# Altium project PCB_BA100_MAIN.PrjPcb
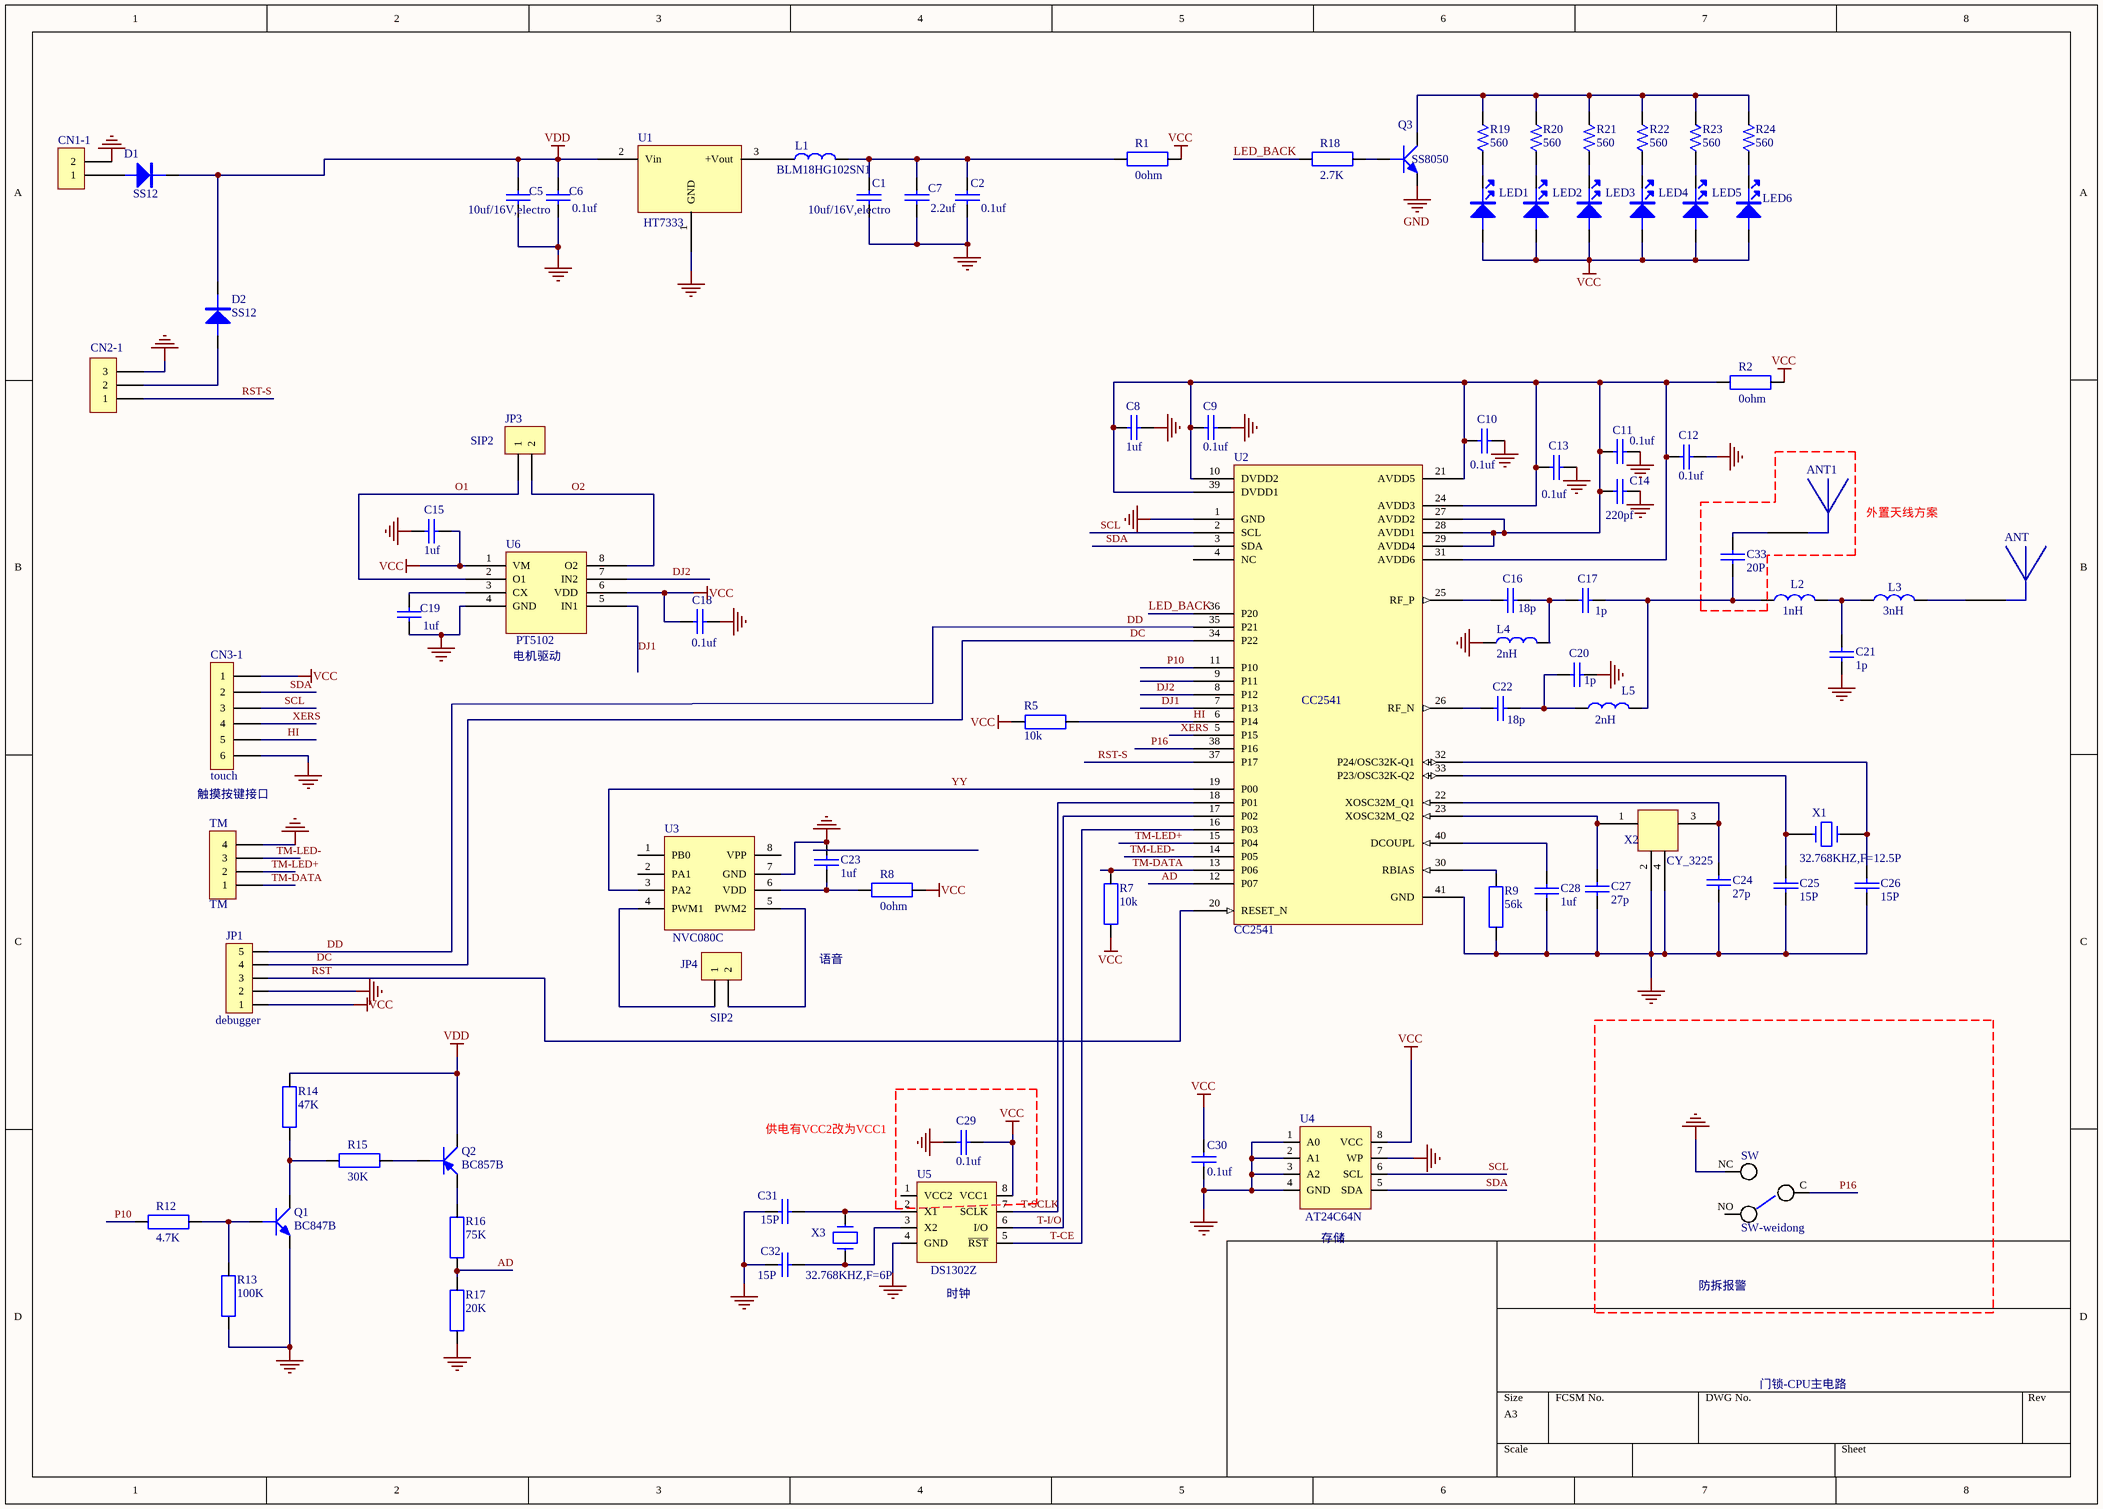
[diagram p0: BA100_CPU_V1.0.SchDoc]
1 sheet, 85 parts. Net scope: global (net labels, ports and power ports of the same name join across sheets).
Board file: BA100_CPU_V1.0.PcbDoc

## Sheet BA100_CPU_V1.0.SchDoc
size A3

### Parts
ANT  ANT  [ANT]  (value not drawn)
ANT1  ANT  [IPEX]  (value not drawn)
C1  10uf/16V,electro  [ECAP_10U_4.3*4.3]
C2  0.1uf  [PC7-*****-KO-0A_0603_TDK]
C5  10uf/16V,electro  [ECAP_10U_4.3*4.3]
C6  0.1uf  [PC5-*****-**-0A_0603_TDK]
C7  2.2uf  [PC5-*****-**-0A_0603_TDK]
C8  1uf  [PC5-*****-**-0A_0603_TDK]
C9  0.1uf  [PC7-*****-KO-0A_0603_TDK]
C10  0.1uf  [PC5-*****-**-0A_0603_TDK]
C11  0.1uf  [PC7-*****-KQA0A_0402_YAGEO]
C12  0.1uf  [PC7-*****-KQA0A_0402_YAGEO]
C13  0.1uf  [PC7-*****-KQA0A_0402_YAGEO]
C14  220pf  [PC7-*****-KQA0A_0402_YAGEO]
C15  1uf  [PC5-*****-**-0A_0603_TDK]
C16  18p  [PC7-*****-KQA0A_0402_YAGEO]
C17  1p  [PC7-*****-KQA0A_0402_YAGEO]
C18  0.1uf  [PC5-*****-**-0A_0603_TDK]
C19  1uf  [PC5-*****-**-0A_0603_TDK]
C20  1p  [PC7-*****-KQA0A_0402_YAGEO]
C21  1p  [PC7-*****-KQA0A_0402_YAGEO]
C22  18p  [PC7-*****-KQA0A_0402_YAGEO]
C23  1uf  [PC5-*****-**-0A_0603_TDK]
C24  27p  [PC7-*****-KO-0A_0603_TDK]
C25  15P  [PC5-*****-**-0A_0603_TDK]
C26  15P  [PC7-*****-KO-0A_0603_TDK]
C27  27p  [PC7-*****-KO-0A_0603_TDK]
C28  1uf  [PC5-*****-**-0A_0603_TDK]
C29  0.1uf  [PC7-*****-KO-0A_0603_TDK]
C30  0.1uf  [PC5-*****-**-0A_0603_TDK]
C31  15P  [PC7-*****-KO-0A_0603_TDK]
C32  15P  [PC7-*****-KO-0A_0603_TDK]
C33  20P  [PC7-*****-KQA0A_0402_YAGEO]
CN1-1  CN1  [PH2.0-2PIN-SMT]  (value not drawn)
CN2-1  CN2  [PH2.0-3PIN-SMT]  (value not drawn)
CN3-1  touch  [PH1.25-6PIN-SMT]
D1  SS12  [SS12-DIDEO]
D2  SS12  [SS12-DIDEO]
JP1  debugger  [ISCP-5PIN]
JP3  SIP2  [PH2.0-2PIN-LSMT1]
JP4  SIP2  [PH2.0-2PIN-LSMT1]
L1  BLM18HG102SN1  [PC7-*****-KO-0A_0603_TDK]
L2  1nH  [PC5-*****-**-0A_0402_TDK]
L3  3nH  [PC5-*****-**-0A_0402_TDK]
L4  2nH  [PC5-*****-**-0A_0402_TDK]
L5  2nH  [PC5-*****-**-0A_0402_TDK]
LED1  MA2X335  [LED-0805]  (value not drawn)
LED2  MA2X335  [LED-0805]  (value not drawn)
LED3  MA2X335  [LED-0805]  (value not drawn)
LED4  MA2X335  [LED-0805]  (value not drawn)
LED5  MA2X335  [LED-0805]  (value not drawn)
LED6  MA2X335  [LED-0805]  (value not drawn)
Q1  BC847B  [PTR-C0025-00-2A_2SC1623]
Q2  BC857B  [PTR-C0025-00-2A_2SC1623]
Q3  SS8050  [PTR-C0025-00-2A_2SC1623]
R1  0ohm  [PRC-*****-AM-0A_0603]
R2  0ohm  [PRC-*****-AM-0A_0603]
R5  10k  [PRC-*****-AM-0A_0603]
R7  10k  [PRC-*****-AM-0A_0603]
R8  0ohm  [PRC-*****-AM-0A_0603]
R9  56k  [PRC-*****-BM-0A_0402]
R12  4.7K  [PRC-*****-AM-0A_0603]
R13  100K  [PRC-*****-AM-0A_0603]
R14  47K  [PRC-*****-AM-0A_0603]
R15  30K  [PRC-*****-AM-0A_0603]
R16  75K  [PRC-*****-AM-0A_0603]
R17  20K  [PRC-*****-AM-0A_0603]
R18  2.7K  [PRC-*****-AM-0A_0603]
R19  560  [PRC-*****-AM-0A_0603]
R20  560  [PRC-*****-AM-0A_0603]
R21  560  [PRC-*****-AM-0A_0603]
R22  560  [PRC-*****-AM-0A_0603]
R23  560  [PRC-*****-AM-0A_0603]
R24  560  [PRC-*****-AM-0A_0603]
SW  SW-weidong  [SW-weidong]
TM  TM  [PH2.0-4PIN-SMT]
U1  HT7333  [SOT89]
U2  CC2541  [CC2530_QFN40]
U3  NVC080C  [SOP-8]
U4  AT24C64N  [PIC-00570-40-2A_93LC46B]
U5  DS1302Z  [PIC-00570-40-2A_93LC46B]
U6  PT5102  [PT5102]
X1  32.768KHZ,F=12.5P  [FC-135]
X2  CY_3225  [CY_3225]
X3  32.768KHZ,F=6P  [FC-135]

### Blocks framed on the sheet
防拆报警: SW

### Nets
GND: C1.1 C2.1 C5.1 C6.1 C7.2 C8.2 C9.2 C10.2 C11.2 C12.2 C13.2 C14.1 C15.1 C18.1 C19.1 C20.2 C21.1 C23.2 C24.1 C25.1 C26.1 C27.1 C28.1 C29.2 C30.1 C31.2 C32.2 CN1-1.2 CN2-1.3 CN3-1.6 JP1.2 L4.1 Q1.E Q3.E R9.2 R13.1 R17.1 SW.NC TM.4 U1.1(GND) U2.1(GND) U2.41(GND) U3.7(GND) U4.1(A0) U4.2(A1) U4.3(A2) U4.4(GND) U4.7(WP) U5.4(GND) U6.4(GND) X2.2 X2.4
VCC: C15.2 C18.2 C29.1 C30.2 CN3-1.1 JP1.1 LED1.A LED2.A LED3.A LED4.A LED5.A LED6.A R1.2 R2.2 R5.1 R7.1 R8.2 U4.8(VCC) U5.8(VCC1) U6.1(VM) U6.6(VDD)
VDD: C5.2 C6.2 D1.1 D2.1 Q2.C R14.2 U1.2(Vin)
AD: R16.1 R17.2 U2.12(P07)
DC: JP1.4 U2.34(P22)
DD: JP1.5 U2.35(P21)
DJ1: U2.7(P13) U6.5(IN1)
DJ2: U2.8(P12) U6.7(IN2)
HI: CN3-1.5 R5.2 U2.6(P14)
LED_BACK: R18.1 U2.36(P20)
O1: JP3.1 U6.2(O1)
O2: JP3.2 U6.8(O2)
P10: R12.1 U2.11(P10)
P16: SW.C U2.38(P16)
RST: JP1.3 U2.20(RESET_N)
RST-S: CN2-1.1 U2.37(P17)
SCL: CN3-1.3 U2.2(SCL) U4.6(SCL)
SDA: CN3-1.2 U2.3(SDA) U4.5(SDA)
T-CE: U2.16(P03) U5.5(~{RST})
T-I/O: U2.17(P02) U5.6(I/O)
T-SCLK: U2.18(P01) U5.7(SCLK)
TM-DATA: R7.2 TM.1 U2.13(P06)
TM-LED+: TM.2 U2.15(P04)
TM-LED-: TM.3 U2.14(P05)
XERS: CN3-1.4 U2.5(P15)
YY: U2.19(P00) U3.3(PA2)
NetANT1_1: ANT1.1 C33.2
NetANT_1: ANT.1 L3.2
NetC1_2: C1.2 C2.2 C7.1 L1.2 R1.1
NetC8_1: C8.1 C9.1 C10.1 C11.1 C12.1 C13.1 C14.2 R2.1 U2.10(DVDD2) U2.21(AVDD5) U2.24(AVDD3) U2.27(AVDD2) U2.28(AVDD1) U2.29(AVDD4) U2.31(AVDD6) U2.39(DVDD1)
NetC16_1: C16.1 U2.25(RF_P)
NetC16_2: C16.2 C17.1 L4.2
NetC17_2: C17.2 C33.1 L2.1 L5.2
NetC19_2: C19.2 U6.3(CX)
NetC20_1: C20.1 C22.2 L5.1
NetC21_2: C21.2 L2.2 L3.1
NetC22_1: C22.1 U2.26(RF_N)
NetC23_1: C23.1 R8.1 U3.6(VDD)
NetC24_2: C24.2 U2.22(XOSC32M_Q1) X2.3
NetC25_2: C25.2 U2.33(P23/OSC32K-Q2) X1.1
NetC26_2: C26.2 U2.32(P24/OSC32K-Q1) X1.2
NetC27_2: C27.2 U2.23(XOSC32M_Q2) X2.1
NetC28_2: C28.2 U2.40(DCOUPL)
NetC31_1: C31.1 U5.2(X1) X3.2
NetC32_1: C32.1 U5.3(X2) X3.1
NetCN1-1_1: CN1-1.1 D1.2
NetCN2-1_2: CN2-1.2 D2.2
NetJP4_1: JP4.1 U3.4(PWM1)
NetJP4_2: JP4.2 U3.5(PWM2)
NetL1_1: L1.1 U1.3(+Vout)
NetLED1_C: LED1.C R19.1
NetLED2_C: LED2.C R20.1
NetLED3_C: LED3.C R21.1
NetLED4_C: LED4.C R22.1
NetLED5_C: LED5.C R23.1
NetLED6_C: LED6.C R24.1
NetQ1_B: Q1.B R12.2 R13.2
NetQ1_C: Q1.C R14.1 R15.1
NetQ2_B: Q2.B R15.2
NetQ2_E: Q2.E R16.2
NetQ3_B: Q3.B R18.2
NetQ3_C: Q3.C R19.2 R20.2 R21.2 R22.2 R23.2 R24.2
NetR9_1: R9.1 U2.30(RBIAS)

Not connected (* = marked no-connect by the designer): SW NO(2); U2 4(NC) 9(P11); U3 1(PB0) 2(PA1) 8(VPP); U5 1(VCC2)

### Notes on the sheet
- 外置天线方案
- (near U6) 电机驱动
- 触摸按键接口
- 语音
- 供电有VCC2改为VCC1
- (near U4) 存储
- (near U5) 时钟
- 门锁-CPU主电路

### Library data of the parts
C1 C2 C5-C33 = PC7_0402_YAGEO: PC7-*****-KQA0A
CN1-1 JP3 JP4 = CON2: Connector
CN2-1 = JP1_E524.03
CN3-1 = CON6
D1 D2 = PDD_SD101CWS: PDD-00330-00-2A
JP1 = CON5
L1-L5 = PWL_18nH: PWL-00195-00-20
LED1-LED6 = PDD_MA2X335: LED
Q1 = PTR_2SC3356: PTR-C0028-00-2A
Q2 = PTR-PNP
Q3 = PTR_2SC5344SF-Y: PTR-C0230-00-20**
R1 R2 R5 R7-R9 R12-R18 = PRC_0603: PRC-*****-AM-0A_0603; Text Field1: pristel=\Models.lib
R19-R24 = RES
TM = HDR1X4 ***
U1 = LM117K
U3 = NV040C
U5 = DS1302
U6 = Component_1_1
X1 = CRYSTAL
X3 = PTR_16MHZ: PTR-X0320-20-2A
